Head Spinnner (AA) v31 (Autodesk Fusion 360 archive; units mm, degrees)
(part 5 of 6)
sketch "Female Battery Hole Extrude" plane through (0, 0, 0) normal (0, 0, 1) x axis (-1, 0, 0)
  curve K1 (-12.6524, -62.4018) -> (-7.672, -65.8891)
  line L1 (-22.2167, -8.1598) -> (-12.6524, -62.4018)
  curve K2 (-18.7294, -3.1795) -> (-22.2167, -8.1598)
  line L2 (40.2396, 7.2184) -> (-18.7294, -3.1795)
  curve K3 (45.2199, 3.7311) -> (40.2396, 7.2184)
  line L3 (54.7843, -50.5109) -> (45.2199, 3.7311)
  curve K4 (51.297, -55.4912) -> (54.7843, -50.5109)
  line L4 (-7.672, -65.8891) -> (51.297, -55.4912)
  line L5 (-17.3761, 80.7925) -> (-11.3045, 81.8631)
  line L6 (-17.8953, 83.7374) -> (-17.3761, 80.7925)
  line L7 (-11.8237, 84.808) -> (-17.8953, 83.7374)
  line L8 (-11.3045, 81.8631) -> (-11.8237, 84.808)
  line L9 (85.5727, 3.0826) -> (82.5824, 3.0826)
  line L10 (85.5727, -3.0826) -> (85.5727, 3.0826)
  line L11 (82.5824, -3.0826) -> (85.5727, -3.0826)
  line L12 (82.5824, 3.0826) -> (82.5824, -3.0826)
  line L13 (-19.3992, -80.3308) -> (-25.3341, -78.661)
  line L14 (-20.2091, -83.2093) -> (-19.3992, -80.3308)
  line L15 (-26.144, -81.5395) -> (-20.2091, -83.2093)
  line L16 (-25.3341, -78.661) -> (-26.144, -81.5395)
  line L17 (-55.9395, 9.9372) -> (-55.803, 9.163)
  line L18 (-39.2687, 12.0784) -> (-39.4052, 12.8526)
  line L19 (-32.6329, -25.5549) -> (-32.7694, -24.7807)
  line L20 (-49.3038, -27.6962) -> (-49.1673, -28.4703)
  line L21 (-27.4486, 68.7829) -> (-24.3215, 51.0478)
  curve K5 (-27.4486, 68.7829) -> (-27.4528, 68.8072)
  curve K6 (-27.4528, 68.8072) -> (-25.9276, 70.9853)
  curve K7 (-25.9276, 70.9853) -> (-25.9034, 70.9897)
  line L22 (0.0613, 75.568) -> (-25.9034, 70.9897)
  curve K8 (0.0613, 75.568) -> (0.0856, 75.5721)
  curve K9 (0.0856, 75.5721) -> (2.2637, 74.047)
  curve K10 (2.2637, 74.047) -> (2.2681, 74.0227)
  line L23 (5.3953, 56.2877) -> (2.2681, 74.0227)
  curve K11 (5.3953, 56.2877) -> (5.3994, 56.2634)
  curve K12 (5.3994, 56.2634) -> (3.8743, 54.0853)
  curve K13 (3.8743, 54.0853) -> (3.8501, 54.0809)
  line L24 (-22.1146, 49.5026) -> (3.8501, 54.0809)
  curve K14 (-22.1146, 49.5026) -> (-22.1389, 49.4985)
  curve K15 (-22.1389, 49.4985) -> (-24.317, 51.0236)
  curve K16 (-24.317, 51.0236) -> (-24.3215, 51.0478)
  line L25 (51.5523, -28.2749) -> (50.8842, -28.3927)
  line L26 (60.5772, -26.6836) -> (51.5523, -28.2749)
  line L27 (58.8129, -16.6779) -> (60.5772, -26.6836)
  line L28 (49.12, -18.3871) -> (58.8129, -16.6779)
  line L29 (50.8842, -28.3927) -> (49.12, -18.3871)
  line L30 (8.4191, 15.2675) -> (10.7551, 2.0195)
  line L31 (8.4191, 15.2675) -> (10.7551, 2.0195)
  line L32 (-18.3167, -30.278) -> (-28.0097, -31.9871)
  line L33 (-28.0097, -31.9871) -> (-26.2454, -41.9928)
  line L34 (-26.2454, -41.9928) -> (-17.2205, -40.4014)
  line L35 (-16.5524, -40.2836) -> (-17.2205, -40.4014)
  circle C1 centre (-22.1247, -36.1078) radius 1.5
  circle C2 centre (14.6103, -82.8593) radius 1.804
  circle C3 centre (-49.1147, 68.3144) radius 1.804
  circle C4 centre (22.7878, 80.9928) radius 1.804
  circle C5 centre (-55.6726, -63.0847) radius 1.804
  circle C6 centre (73.8914, -40.2391) radius 1.804
  circle C7 centre (-84.0329, 4.1939) radius 1.804
  circle C8 centre (77.5307, 32.6819) radius 1.804
  circle C9 centre (0, 0) radius 88.9
  arc A1 centre (-44.2862, -7.8089) radius 20.5105 clockwise from (-49.3038, -27.6962) to (-55.803, 9.163)
  arc A2 centre (-47.6724, 11.3949) radius 8.3947 clockwise from (-55.9395, 9.9372) to (-39.4052, 12.8526)
  arc A3 centre (-44.2862, -7.8089) radius 20.5105 clockwise from (-39.2687, 12.0784) to (-32.7694, -24.7807)
  arc A4 centre (-40.9001, -27.0126) radius 8.3947 clockwise from (-32.6329, -25.5549) to (-49.1673, -28.4703)
  circle C10 centre (54.6922, -22.5629) radius 1.5
  point P58 (50.8842, -28.3927)
  point P62 (49.12, -18.3871)
  point P63 (50.0021, -23.3899)
  point P65 (10.7551, 2.0195)
  point P59 (51.5523, -28.2749)
  point P72 (-17.2205, -40.4014)
  point P60 (60.5772, -26.6836)
  point P71 (-26.2454, -41.9928)
  point P61 (58.8129, -16.6779)
  point P69 (-28.0097, -31.9871)
  point P70 (-18.3167, -30.278)
  point P67 (10.7551, 2.0195)
  point P66 (8.4191, 15.2675)
  point P68 (8.4191, 15.2675)
  point P73 (-16.5524, -40.2836)
  point P64 (54.6922, -22.5629)
  coincident L3 P58
  perpendicular L3 L25
  perpendicular L3 L26
  perpendicular L26 L27
  coincident L3 P62
  perpendicular L3 L28
  midpoint L29 P63
  midpoint L3 P63
  midpoint L2 P65
  perpendicular L2 L30
  symmetric P59 L30 P72
  symmetric P60 L30 P71
  symmetric P61 L30 P69
  symmetric P62 L30 P70
  symmetric P65 L30 P67
  symmetric P66 L30 P68
  coincident L1 P73
  perpendicular L1 L35
  dimension "d581" distance L28 P64 = 5.08
  dimension "d582" distance L27 P64 = 5.08
extrude "Extrude44" add sketch "Female Battery Hole Extrude" profile of C1 L1 L3 L25 L26 L27 L28 L29 C10 L32 L33 L34 L35 along normal blind 6.35
chamfer "Chamfer4" distance 1.524
fillet "Fillet8" radius 2.54
chamfer "Chamfer8" distance 1.27
sketch "Battery Hole Shrink" plane through (0, 0, -0.635) normal (0, 0, -1) x axis (1, 0, 0)
  line L1 (21.9717, -8.4882) -> (26.8326, -36.0558)
  curve K1 (21.9445, -7.8065) -> (21.9717, -8.4882)
  curve K2 (21.9445, -7.8065) -> (18.6743, -3.4921)
  line L2 (-40.2947, 6.9057) -> (18.6743, -3.4921)
  curve K3 (-40.2947, 6.9057) -> (-44.8427, 3.9746)
  curve K4 (-45.1031, 3.3367) -> (-44.8427, 3.9746)
  line L3 (-59.0984, -20.9038) -> (-45.1031, 3.3367)
  line L4 (-54.5392, -50.1825) -> (-59.4001, -22.6149)
  curve K5 (-54.512, -50.8642) -> (-54.5392, -50.1825)
  curve K6 (-54.512, -50.8642) -> (-51.2418, -55.1786)
  line L5 (7.7272, -65.5764) -> (-51.2418, -55.1786)
  curve K7 (7.7272, -65.5764) -> (12.2752, -62.6453)
  curve K8 (12.5356, -62.0074) -> (12.2752, -62.6453)
  line L6 (26.5309, -37.7669) -> (12.5356, -62.0074)
  curve K9 (-42.7185, 3.29) -> (-40.6806, 4.717)
  line L7 (18.2884, -5.6809) -> (-40.6806, 4.717)
  curve K10 (18.2884, -5.6809) -> (19.7153, -7.7188)
  line L8 (10.151, -61.9607) -> (19.7153, -7.7188)
  curve K11 (10.151, -61.9607) -> (8.1131, -63.3877)
  line L9 (-50.8559, -52.9898) -> (8.1131, -63.3877)
  curve K12 (-50.8559, -52.9898) -> (-52.2828, -50.9519)
  line L10 (-42.7185, 3.29) -> (-52.2828, -50.9519)
  circle C1 centre (-54.6922, -22.5629) radius 1.5
  circle C2 centre (22.1247, -36.1078) radius 1.5
  arc A1 centre (24.3312, -36.4969) radius 2.54 clockwise from (26.8326, -36.0558) to (26.5309, -37.7669)
  arc A2 centre (-56.8987, -22.1738) radius 2.54 clockwise from (-59.4001, -22.6149) to (-59.0984, -20.9038)
  circle C3 centre (-54.6922, -22.5629) radius 1.45
  circle C4 centre (22.1247, -36.1078) radius 1.45
  concentric C1 C3
  concentric C2 C4
  equal C3 C4
  dimension "d588" diameter C3 = 2.9
extrude "Extrude45" add sketch "Battery Hole Shrink" profile of C1 C2 C3 C4 against normal blind 6.985
remove_instance "RemoveInstance1"
sketch "AAA Battey Holder Wires" plane through (0.021, -0.1193, 0) normal (0.1736, -0.9848, 0) x axis (0.9848, 0.1736, 0)
  line L1 (18.997, 1.27) -> (-40.8817, 1.27)
  line L2 (18.997, 17.78) -> (18.997, 1.27)
  line L3 (-40.8817, 17.78) -> (18.997, 17.78)
  line L4 (-40.8817, 1.27) -> (-40.8817, 17.78)
  line L5 (3.7077, 0.54) -> (3.7077, 7.54)
  line L6 (4.9577, 7.54) -> (4.9577, 0.54)
  line L7 (5.5162, 15.24) -> (14.4062, 15.24)
  line L8 (-12.7111, 15.24) -> (5.5162, 15.24)
  line L9 (4.9577, 7.54) -> (3.7077, 7.54)
  line L10 (4.3327, 16.8158) -> (4.3327, 7.54)
  line L11 (10.6827, 15.24) -> (-2.0173, 15.24)
  line L12 (10.6827, 10.795) -> (10.6827, 15.24)
  line L13 (-2.0173, 10.795) -> (10.6827, 10.795)
  line L14 (-2.0173, 15.24) -> (-2.0173, 10.795)
  point P13 (5.5162, 15.24)
  point P14 (5.5162, 15.24)
  point P11 (3.7077, 7.54)
  point P16 (3.7077, 7.54)
  point P10 (4.9577, 7.54)
  point P17 (4.9577, 7.54)
  point P18 (4.3327, 7.54)
  point P24 (4.3327, 15.24)
  point P22 (10.6827, 10.795)
  point P23 (-2.0173, 10.795)
  point P20 (-2.0173, 15.24)
  coincident P13 P14
  parallel L7 L8
  coincident P11 P16
  coincident P10 P17
  midpoint L9 P18
  perpendicular L8 L10
  horizontal L11
  vertical L12
  horizontal L13
  vertical L14
  midpoint L11 P24
  coincident L8 P24
  coincident L10 P24
  dimension "d591" distance P22 P23 = 12.7
  dimension "d592" distance P20 P23 = 4.445
extrude "Extrude46" cut sketch "AAA Battey Holder Wires" profile of L7 L11 L12 L13 L14 against normal blind 10.16
component_from_bodies "Body->Comp4"
sketch "Motor Switch Fill" plane through (0, 0, 12.7) normal (0, 0, 1) x axis (-1, 0, 0)
  line L1 (-1.252, 71.3831) -> (-23.238, 67.5064)
  line L2 (1.1847, 57.5642) -> (-1.252, 71.3831)
  line L3 (-20.8014, 53.6874) -> (1.1847, 57.5642)
  line L4 (-23.238, 67.5064) -> (-20.8014, 53.6874)
  line L5 (1.085, 73.8986) -> (4.241, 55.9997)
  line L6 (-25.7793, 69.8065) -> (0.3493, 74.4137)
  line L7 (-23.1383, 51.172) -> (-26.2943, 69.0709)
  line L8 (3.7259, 55.2641) -> (-22.4027, 50.6569)
  line L9 (-21.5225, 52.6576) -> (2.2146, 56.8431)
  line L10 (-24.2679, 68.2275) -> (-21.5225, 52.6576)
  line L11 (-0.5308, 72.413) -> (-24.2679, 68.2275)
  line L12 (2.2146, 56.8431) -> (-0.5308, 72.413)
  line L13 (-20.6983, 53.8346) -> (1.0376, 57.6672)
  line L14 (-23.0909, 67.4034) -> (-20.6983, 53.8346)
  line L15 (-1.355, 71.236) -> (-23.0909, 67.4034)
  line L16 (1.0376, 57.6672) -> (-1.355, 71.236)
  line L17 (-1.5314, 72.2366) -> (-1.3071, 70.9646)
  line L18 (1.214, 56.6666) -> (1.0376, 57.6672)
  line L19 (-20.5219, 52.834) -> (-20.6983, 53.8346)
  line L20 (-23.2673, 68.4039) -> (-23.0909, 67.4034)
  closed curve K1 centre (3.6157, 55.8894)
  closed curve K2 centre (0.4596, 73.7883)
  closed curve K3 centre (-25.669, 69.1812)
  closed curve K4 centre (-22.5129, 51.2822)
  point P26 (-1.3071, 70.9646)
  point P27 (-1.5314, 72.2366)
  point P28 (1.214, 56.6666)
  point P29 (-20.5219, 52.834)
  point P30 (-23.2673, 68.4039)
  coincident L16 P26
  coincident L11 P27
  perpendicular L11 L17
  coincident L9 P28
  perpendicular L9 L18
  coincident L9 P29
  perpendicular L9 L19
  coincident L11 P30
  perpendicular L11 L20
  dimension "d595" = -0.889
  dimension "d596" = 0.127 (= "clearance / 2")
extrude "Extrude47" add sketch "Motor Switch Fill" profile of L12 L10 L9 L11 L16 L14 L17 L18 L19 L20 against normal blind 15.24
sketch "Pot Flat Face Cut" plane through (-88.9, 0, 0) normal (1, 0, 0) x axis (0, 1, 0)
  curve K1 (0, 41.9735) -> (0, 34.2265)
  curve K2 (0, 34.2265) -> (0, 41.9735)
  line L1 (0, 41.9735) -> (0, 34.2265)
  circle C1 centre (0, 38.1) radius 5.8102
  point P2 (0, 34.2265)
  point P5 (0, 34.2265)
  point P3 (0, 41.9735)
  point P6 (0, 41.9735)
  point P4 (0, 38.1)
  coincident P2 P5
  coincident P3 P6
  midpoint P4 L1
  dimension "d629" diameter C1 = 11.6205
extrude "Extrude11" cut sketch "Pot Flat Face Cut" profile of K1 K2 C1 along normal blind 0.254
chamfer "Chamfer6" distance 0.254
fillet "Fillet1" radius 0.635
sketch "Motor Controller Housing Material Cut" plane through (-58.7622, 0, 0) normal (1, 0, 0) x axis (0, 1, 0)
  line L1 (-16.2941, 60.325) -> (16.2941, 60.325)
  line L2 (-16.2941, 51.4477) -> (-16.2941, 60.325)
  line L3 (16.2941, 51.4477) -> (-16.2941, 51.4477)
  line L4 (16.2941, 60.325) -> (16.2941, 51.4477)
  line L5 (-1.397, 55.2577) -> (1.397, 55.2577)
  line L6 (-1.397, 60.325) -> (-1.397, 55.2577)
  line L7 (1.397, 60.325) -> (-1.397, 60.325)
  line L8 (1.397, 55.2577) -> (1.397, 60.325)
  line L9 (-7.493, 55.2577) -> (-7.493, 60.325)
  line L10 (-10.287, 55.2577) -> (-7.493, 55.2577)
  line L11 (-10.287, 60.325) -> (-10.287, 55.2577)
  line L12 (10.287, 55.2577) -> (10.287, 60.325)
  line L13 (7.493, 55.2577) -> (10.287, 55.2577)
  line L14 (7.493, 60.325) -> (7.493, 55.2577)
  line L15 (-16.2941, 55.2577) -> (16.2941, 55.2577)
  point P8 (-1.397, 60.325)
  point P10 (0, 60.325)
  point P11 (0, 60.325)
  point P20 (16.2941, 55.2577)
  point P21 (-16.2941, 55.2577)
  point P6 (1.397, 55.2577)
  point P7 (-1.397, 55.2577)
  horizontal L5
  vertical L6
  horizontal L7
  vertical L8
  coincident L1 P8
  midpoint L1 P10
  midpoint L7 P11
  coincident P10 P11
  coincident L4 P20
  coincident L2 P21
  perpendicular L2 L15
  collinear L10 L15
  dimension "d635" distance L3 L5 = 3.81
  dimension "d636" distance P6 P7 = 2.794
  dimension "d639" R-Pattern1-uDistance = 8.89
  dimension "d640" R-Pattern1-vDistance = 0
extrude "Extrude12" cut sketch "Motor Controller Housing Material Cut" profile of L1 L2 L4 L6 L8 L9 L11 L12 L14 L15 against normal blind 24.8666
sketch "Gasket" plane through (0, 0, 60.325) normal (0, 0, -1) x axis (1, 0, 0)
  line L1 (-58.7622, 7.493) -> (-58.7622, 10.287)
  line L2 (-83.6288, 7.493) -> (-58.7622, 7.493)
  line L3 (-83.6288, 1.397) -> (-83.6288, 7.493)
  line L4 (-58.7622, 1.397) -> (-83.6288, 1.397)
  line L5 (-58.7622, -1.397) -> (-58.7622, 1.397)
  line L6 (-83.6288, -1.397) -> (-58.7622, -1.397)
  line L7 (-83.6288, -7.493) -> (-83.6288, -1.397)
  line L8 (-58.7622, -7.493) -> (-83.6288, -7.493)
  line L9 (-58.7622, -10.287) -> (-58.7622, -7.493)
  line L10 (-83.6288, -10.287) -> (-58.7622, -10.287)
  line L11 (-83.6288, -16.2941) -> (-83.6288, -10.287)
  line L12 (-58.7622, -16.2941) -> (-83.6288, -16.2941)
  line L13 (-58.7622, -18.8341) -> (-58.7622, -16.2941)
  line L14 (-83.6305, -18.8341) -> (-58.7622, -18.8341)
  line L15 (-58.7622, 18.8341) -> (-83.6305, 18.8341)
  line L16 (-58.7622, 16.2941) -> (-58.7622, 18.8341)
  line L17 (-83.6288, 16.2941) -> (-58.7622, 16.2941)
  line L18 (-83.6288, 10.287) -> (-83.6288, 16.2941)
  line L19 (-58.7622, 10.287) -> (-83.6288, 10.287)
  line L20 (-41.3411, -8.2894) -> (-49.7744, -11.3589)
  line L21 (2.5431, 50.9906) -> (0.9847, 42.1525)
  line L22 (13.4917, 39.9472) -> (15.0501, 48.7853)
  line L23 (42.8876, -27.6977) -> (36.0128, -21.929)
  line L24 (27.8494, -31.6578) -> (34.7242, -37.4264)
  line L25 (-45.4307, -23.293) -> (-36.9975, -20.2235)
  line L26 (-38.7289, 28.933) -> (-35.5184, 26.2391)
  line L27 (-35.2186, 33.1164) -> (-38.7289, 28.933)
  line L28 (-32.0081, 30.4224) -> (-35.2186, 33.1164)
  line L29 (-35.5184, 26.2391) -> (-32.0081, 30.4224)
  line L30 (-11.0703, -47.0584) -> (-5.6923, -48.0067)
  line L31 (-10.3425, -42.9311) -> (-11.0703, -47.0584)
  line L32 (-4.9645, -43.8794) -> (-10.3425, -42.9311)
  line L33 (-5.6923, -48.0067) -> (-4.9645, -43.8794)
  line L34 (44.4212, 19.0737) -> (40.4829, 17.6403)
  line L35 (46.2889, 13.9421) -> (44.4212, 19.0737)
  line L36 (42.3507, 12.5086) -> (46.2889, 13.9421)
  line L37 (40.4829, 17.6403) -> (42.3507, 12.5086)
  line L38 (-45.554, -23.6081) -> (-37.1151, -20.5366)
  line L39 (27.8529, -31.9922) -> (34.7323, -37.7648)
  line L40 (43.2222, -27.6469) -> (36.3428, -21.8743)
  line L41 (13.7797, 40.1174) -> (15.3391, 48.9614)
  line L42 (2.3318, 51.255) -> (0.7723, 42.411)
  line L43 (-41.6325, -8.1252) -> (-50.0714, -11.1967)
  line L44 (-31.6503, 30.4537) -> (-35.2499, 33.4742)
  line L45 (-35.4871, 25.8812) -> (-31.6503, 30.4537)
  line L46 (-39.0867, 28.9017) -> (-35.4871, 25.8812)
  line L47 (-35.2499, 33.4742) -> (-39.0867, 28.9017)
  line L48 (-4.6702, -43.6733) -> (-10.5486, -42.6368)
  line L49 (-5.4862, -48.301) -> (-4.6702, -43.6733)
  line L50 (-11.3645, -47.2644) -> (-5.4862, -48.301)
  line L51 (-10.5486, -42.6368) -> (-11.3645, -47.2644)
  line L52 (44.573, 19.3993) -> (40.1573, 17.7921)
  line L53 (46.6145, 13.7902) -> (44.573, 19.3993)
  line L54 (42.1989, 12.1831) -> (46.6145, 13.7902)
  line L55 (40.1573, 17.7921) -> (42.1989, 12.1831)
  circle C1 centre (55.6548, -57.4817) radius 1.5875
  circle C2 centre (43.6561, -67.0503) radius 1.5875
  circle C3 centre (-10.2408, -79.3519) radius 1.5875
  circle C4 centre (-25.2029, -75.9369) radius 1.5875
  circle C5 centre (-68.4248, -41.4686) radius 1.5875
  circle C6 centre (-75.0836, -27.6415) radius 1.5875
  circle C7 centre (-75.0836, 27.6415) radius 1.5875
  circle C8 centre (-68.4248, 41.4686) radius 1.5875
  circle C9 centre (-25.2029, 75.9369) radius 1.5875
  circle C10 centre (-10.2408, 79.3519) radius 1.5875
  circle C11 centre (43.6561, 67.0503) radius 1.5875
  circle C12 centre (55.6548, 57.4817) radius 1.5875
  circle C13 centre (79.6412, 7.6735) radius 1.5875
  circle C14 centre (79.6412, -7.6735) radius 1.5875
  circle C15 centre (49.8854, -62.5543) radius 3.6788
  circle C16 centre (-72.0865, 34.715) radius 3.6788
  circle C17 centre (80.01, 0) radius 3.6788
  circle C18 centre (-17.8039, -78.004) radius 3.6788
  circle C19 centre (-17.8039, 78.004) radius 3.6788
  circle C20 centre (49.8854, 62.5543) radius 3.6788
  circle C21 centre (-72.0865, -34.715) radius 3.6788
  arc A1 centre (0, 0) radius 85.725 clockwise from (-83.6305, 18.8341) to (-83.6305, -18.8341)
  arc A2 centre (0, 0) radius 51.054 clockwise from (-45.4307, -23.293) to (-49.7744, -11.3589)
  arc A3 centre (0, 0) radius 42.164 clockwise from (-41.3411, -8.2894) to (0.9847, 42.1525)
  arc A4 centre (0, 0) radius 51.054 clockwise from (2.5431, 50.9906) to (15.0501, 48.7853)
  arc A5 centre (0, 0) radius 42.164 clockwise from (13.4917, 39.9472) to (36.0128, -21.929)
  arc A6 centre (0, 0) radius 51.054 clockwise from (42.8876, -27.6977) to (34.7242, -37.4264)
  arc A7 centre (0, 0) radius 42.164 clockwise from (27.8494, -31.6578) to (-36.9975, -20.2235)
  circle C22 centre (0, 0) radius 42.9895
  circle C23 centre (0, 0) radius 54.229
  arc A8 centre (0, 0) radius 51.308 clockwise from (-45.554, -23.6081) to (-50.0714, -11.1967)
  arc A9 centre (0, 0) radius 42.418 clockwise from (27.8529, -31.9922) to (-37.1151, -20.5366)
  arc A10 centre (0, 0) radius 51.308 clockwise from (43.2222, -27.6469) to (34.7323, -37.7648)
  arc A11 centre (0, 0) radius 42.418 clockwise from (13.7797, 40.1174) to (36.3428, -21.8743)
  arc A12 centre (0, 0) radius 51.308 clockwise from (2.3318, 51.255) to (15.3391, 48.9614)
  arc A13 centre (0, 0) radius 42.418 clockwise from (-41.6325, -8.1252) to (0.7723, 42.411)
  concentric A1 C22
  concentric A1 C23
  dimension "d651" distance A7 C22 = 0.8255
  dimension "d653" distance A6 C23 = 3.175
extrude "Extrude1" new body sketch "Gasket" profile of C22 C23 A8 L40 L38 L39 A10 L41 A12 L42 L43 L44 L47 L45 L46 L48 L49 L50 L51 L52 L54 L53 L55 along normal blind 3.175
sketch "Revolve Limit" plane through (0, 0, 57.15) normal (0, 0, -1) x axis (1, 0, 0)
  line L1 (-45.554, -23.6081) -> (-37.6587, -20.7345)
  line L2 (-42.1761, -8.323) -> (-50.0714, -11.1967)
  line L3 (2.3318, 51.255) -> (0.8728, 42.9806)
  line L4 (13.8801, 40.6871) -> (15.3391, 48.9614)
  line L5 (43.2222, -27.6469) -> (36.7859, -22.2462)
  line L6 (28.296, -32.3641) -> (34.7323, -37.7648)
  line L7 (42.1989, 12.1831) -> (46.6145, 13.7902)
  line L8 (40.1573, 17.7921) -> (42.1989, 12.1831)
  line L9 (44.573, 19.3993) -> (40.1573, 17.7921)
  line L10 (46.6145, 13.7902) -> (44.573, 19.3993)
  line L11 (-39.0867, 28.9017) -> (-35.4871, 25.8812)
  line L12 (-35.2499, 33.4742) -> (-39.0867, 28.9017)
  line L13 (-31.6503, 30.4537) -> (-35.2499, 33.4742)
  line L14 (-35.4871, 25.8812) -> (-31.6503, 30.4537)
  line L15 (-11.3645, -47.2644) -> (-5.4862, -48.301)
  line L16 (-10.5486, -42.6368) -> (-11.3645, -47.2644)
  line L17 (-4.6702, -43.6733) -> (-10.5486, -42.6368)
  line L18 (-5.4862, -48.301) -> (-4.6702, -43.6733)
  arc A1 centre (0, 0) radius 42.9895 clockwise from (28.296, -32.3641) to (-37.6587, -20.7345)
  arc A2 centre (0, 0) radius 51.308 clockwise from (-45.554, -23.6081) to (-50.0714, -11.1967)
  arc A3 centre (0, 0) radius 42.9895 clockwise from (-42.1761, -8.323) to (0.8728, 42.9806)
  arc A4 centre (0, 0) radius 51.308 clockwise from (2.3318, 51.255) to (15.3391, 48.9614)
  arc A5 centre (0, 0) radius 42.9895 clockwise from (13.8801, 40.6871) to (36.7859, -22.2462)
  arc A6 centre (0, 0) radius 51.308 clockwise from (43.2222, -27.6469) to (34.7323, -37.7648)
  circle C1 centre (0, 0) radius 54.229
  circle C2 centre (0, 0) radius 51.7525
  concentric A1 C2
  dimension "d660" distance A2 C2 = 0.4445 (= "clearance * 1.75")
sketch "Gasket Revolve Profile" plane through (0, 0, 0) normal (1, 0, 0) x axis (0, 1, 0)
  line L1 (51.7525, 57.15) -> (-51.7525, 57.15)
  line L2 (54.229, 57.15) -> (-54.229, 57.15)
  line L3 (54.229, 60.325) -> (-54.229, 60.325)
  line L4 (51.7525, 52.07) -> (54.229, 57.15)
  line L5 (51.7525, 57.15) -> (51.7525, 52.07)
  line L6 (51.054, 52.07) -> (-51.054, 52.07)
  line L7 (51.7525, 57.15) -> (54.229, 57.15)
  point P5 (54.229, 57.15)
  point P8 (54.229, 57.15)
  point P3 (51.7525, 57.15)
  point P10 (51.7525, 57.15)
  point P9 (51.7525, 52.07)
  point P13 (51.7525, 57.15)
  coincident P5 P8
  coincident P3 P10
  perpendicular L2 L5
  coincident P9 L6
  coincident P3 P13
revolve "Revolve1" sketch "Gasket Revolve Profile" AlongAngle 360
chamfer "Chamfer1" distance 0.3175
copy_paste "CutPaste2"
copy_paste "CutPaste3"
copy_paste "CutPaste9"
copy_paste "CutPaste4"
copy_paste "CutPaste1"
copy_paste "CutPaste2"
copy_paste "CutPaste1"
sketch "LED Wire Arc Length" plane through (0, 0, 63.5) normal (0, 0, 1) x axis (-1, 0, 0)
  circle C1 centre (-55.6548, -57.4817) radius 1.5875
  circle C2 centre (-43.6561, -67.0503) radius 1.5875
  circle C3 centre (10.2408, -79.3519) radius 1.5875
  circle C4 centre (25.2029, -75.9369) radius 1.5875
  circle C5 centre (68.4248, -41.4686) radius 1.5875
  circle C6 centre (75.0836, -27.6415) radius 1.5875
  circle C7 centre (75.0836, 27.6415) radius 1.5875
  circle C8 centre (68.4248, 41.4686) radius 1.5875
  circle C9 centre (25.2029, 75.9369) radius 1.5875
  circle C10 centre (10.2408, 79.3519) radius 1.5875
  circle C11 centre (-43.6561, 67.0503) radius 1.5875
  circle C12 centre (-55.6548, 57.4817) radius 1.5875
  circle C13 centre (-79.6412, 7.6735) radius 1.5875
  circle C14 centre (-79.6412, -7.6735) radius 1.5875
  circle C15 centre (-49.8854, -62.5543) radius 3.6788
  circle C16 centre (72.0865, 34.715) radius 3.6788
  circle C17 centre (-80.01, 0) radius 3.6788
  circle C18 centre (17.8039, -78.004) radius 3.6788
  circle C19 centre (17.8039, 78.004) radius 3.6788
  circle C20 centre (-49.8854, 62.5543) radius 3.6788
  circle C21 centre (72.0865, -34.715) radius 3.6788
  circle C22 centre (0, 0) radius 42.164
  circle C23 centre (0, 0) radius 85.725
  arc A1 centre (0, 0) radius 80.01 clockwise from (-49.8854, 62.5543) to (17.8039, 78.004)
  point P12 (-43.6561, 67.0503)
  point P21 (-49.8854, 62.5543)
  point P25 (-49.8854, 62.5543)
  point P20 (17.8039, 78.004)
  point P24 (17.8039, 78.004)
  coincident P12 A1
  coincident P21 P25
  coincident P20 P24
sketch "Sketch81" plane through (0, 0, 63.5) normal (0, 0, 1) x axis (1, 0, 0)
  circle C1 centre (0, 0) radius 41.275
  circle C2 centre (0, 0) radius 42.164
  point P1 (0, 0)
  point P2 (0, 0)
  coincident P1 P2
  dimension "d663" distance C1 C2 = 0.889
extrude "Extrude1" new body sketch "Sketch81" profile of C1 along normal blind 1.5113 bodies "Rubber Circle"
sketch "Sketch1" plane through (0, 0, 3.175) normal (0, 0, 1) x axis (-1, 0, 0)
  circle C1 centre (0, 0) radius 41.91
  circle C2 centre (0, 0) radius 41.275
extrude "Extrude2" cut sketch "Sketch1" against normal blind 20.32
joint "Assemble19" alignAngle 0 alignOffsetX 0 alignOffsetY 0 alignOffsetZ 0
offset_faces "OffsetFaces1" distance -0.7937
component_from_bodies "Body->Comp1"
component_from_bodies "Body->Comp2"
joint "Assemble1" alignAngle 0 alignOffsetX 0 alignOffsetY 0 alignOffsetZ 0
sketch "Sketch82" plane through (0, 0, 64.2176) normal (0, 0, 1) x axis (-1, 0, 0)
  circle C1 centre (0, 0) radius 41.275
  circle C2 centre (0, 0) radius 41.4631
  dimension "d677" = 0.1881 (= "clearance / 1.35")
extrude "Extrude16" new body sketch "Sketch82" along normal blind 1.5875 bodies "Rubber to Plat. Fixture"
sketch "Sketch83" plane through (0, 0, 65.8051) normal (0, 0, 1) x axis (-1, 0, 0)
  circle C1 centre (0, 0) radius 41.4631
  circle C2 centre (0, 0) radius 41.91
  circle C3 centre (0, 0) radius 43.4975
  dimension "d680" = 1.5875
extrude "Extrude17" add sketch "Sketch83" against normal blind 3.81
sketch "Sketch85" plane through (0, 0, 61.9951) normal (0, 0, -1) x axis (1, 0, 0)
  circle C1 centre (0, 0) radius 41.4631
  circle C2 centre (0, 0) radius 43.4975
  circle C3 centre (0, 0) radius 41.91
  circle C4 centre (0, 0) radius 42.6085
  dimension "d686" = 0.6985 (= "clearance * 2.75")
extrude "Extrude19" add sketch "Sketch85" profile of C2 C4 along normal blind 5.969
sketch "Sketch86" plane through (0, 0, 64.2176) normal (0, 0, -1) x axis (1, 0, 0)
  circle C1 centre (0, 0) radius 41.4631
  circle C2 centre (0, 0) radius 31.75
  concentric C1 C2
  dimension "d689" diameter C2 = 63.5
extrude "Extrude20" cut sketch "Sketch86" profile of C2 against normal blind 30.48
offset_faces "OffsetFaces1" distance 0.889
chamfer "Chamfer5" distance 0.635
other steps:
base_feature "Base Feature1" bodies "Rubber Lift"
base_feature "Base Feature1" bodies "Rubber Circle"
base_feature "Base Feature1"
base_feature "Base Feature1" bodies "Rubber Lift"
base_feature "Base Feature1"
base_feature "Base Feature1"
base_feature "Base Feature1" bodies "Shell"
base_feature "Base Feature1" bodies "XY Restriction"
chamfer "Chamfer4" distance 0.8255
extrude "Extrude11" cut sketch "Sketch73" profile of L8 L9 L10 L11 L17 L16 L15 L14 L18 L19 L20 L21 L22 L23 L24 L25 L26 L27 L28 L29 L30 L31 L32 L33 along normal blind 15.24
base_feature "Base Feature1" bodies "Shell"
extrude "Extrude2" cut sketch "Holes for Shell Btm" profile of C4 C5 C6 C7 C8 C9 C10 distance 12.7
extrude "Extrude43" cut sketch "Battery Cover Holes" profile of C1 C2 against normal blind 12.7
create_component "CreateComponent1"
create_component "CreateComponent2"
remove_body "RemoveBody1"
create_component "CreateComponent3"
remove_body "RemoveBody2"
joint_origin "JointOrigin5"
joint_origin "JointOrigin3"
create_component "CreateComponent4"
remove_body "RemoveBody1"
create_component "CreateComponent5"
create_component "CreateComponent6"
joint_origin "JointOrigin3"
joint_origin "JointOrigin4"
joint_origin "JointOrigin6"
joint_origin "JointOrigin8"
joint_origin "JointOrigin7"
create_component "CreateComponent7"
create_component "CreateComponent8"
remove_instance "RemoveInstance1"
remove_instance "RemoveInstance2"
remove_instance "RemoveInstance3"
remove_instance "RemoveInstance4"
create_component "CreateComponent9"
remove_instance "RemoveInstance5"
remove_instance "RemoveInstance6"
create_component "CreateComponent1"
remove_body "RemoveBody1"
remove_instance "RemoveInstance7"
remove_instance "RemoveInstance1"
remove_instance "RemoveInstance8"
remove_instance "RemoveInstance9"
remove_instance "RemoveInstance10"
remove_instance "RemoveInstance11"
joint_origin "JointOrigin8"
create_component "CreateComponent1"
remove_body "RemoveBody1"
joint_origin "JointOrigin9"
joint_origin "JointOrigin1"
create_component "CreateComponent2"
remove_body "RemoveBody2"
joint_origin "JointOrigin7"
joint_origin "JointOrigin8"
joint_origin "JointOrigin9"
joint_origin "JointOrigin3"
joint_origin "JointOrigin10"
remove_instance "RemoveInstance12"
joint_origin "JointOrigin4"
create_component "CreateComponent10"
remove_body "RemoveBody3"
create_component "CreateComponent11"
remove_instance "RemoveInstance13"
remove_instance "RemoveInstance14"
remove_instance "RemoveInstance15"
remove_instance "RemoveInstance16"
remove_instance "RemoveInstance17"
remove_instance "RemoveInstance18"
remove_instance "RemoveInstance19"
create_component "CreateComponent1"
remove_instance "RemoveInstance2" sketch "Profile"
remove_instance "RemoveInstance3" sketch "Profile"
remove_instance "RemoveInstance4"
remove_instance "RemoveInstance5"
joint_origin "JointOrigin12"
remove_body "RemoveBody2"
joint_origin "JointOrigin10"
joint_origin "JointOrigin5"
joint_origin "JointOrigin13"
create_component "CreateComponent13"
remove_body "RemoveBody5"
joint_origin "JointOrigin14"
joint_origin "JointOrigin5"
joint_origin "JointOrigin12"
create_component "CreateComponent14"
remove_instance "RemoveInstance21"
remove_instance "RemoveInstance22"
remove_instance "RemoveInstance23"
remove_instance "RemoveInstance24"
create_component "CreateComponent15"
remove_instance "RemoveInstance25"
remove_instance "RemoveInstance26"
remove_instance "RemoveInstance1"
joint_origin "JointOrigin4"
joint_origin "JointOrigin6"
create_component "CreateComponent1"
remove_body "RemoveBody1"
create_component "CreateComponent2"
remove_body "RemoveBody2"
joint_origin "JointOrigin1"
joint_origin "JointOrigin1"
named bodies: "Shell", "Rubber Lift", "Bottom", "XY Restriction", "Rubber Circle", "Rubber to Plat. Fixture"

design "9V Battery & T Connector"
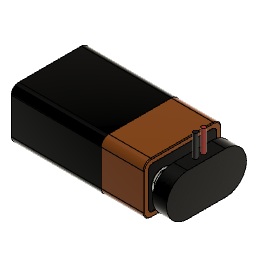
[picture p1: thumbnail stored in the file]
base_feature "Base Feature1"
base_feature "Base Feature1"
base_feature "Base Feature1" bodies "Clip", "Negative", "Positive"
joint "Assemble1" alignAngle 180 alignOffsetX 0 alignOffsetY 0 alignOffsetZ 0.381
move "Move1"
move "Move2"
remove_body "RemoveBody1"
remove_body "RemoveBody2"
sketch "Sketch1" plane through (2.5021, 1.948, 15.621) normal (0, 0, 1) x axis (-1, 0, 0)
  line L1 (-25.3765, -86.0759) -> (-38.0765, -86.0759)
  line L2 (-25.3765, -81.3769) -> (-25.3765, -86.0759)
  line L3 (-38.0765, -81.3769) -> (-25.3765, -81.3769)
  line L4 (-38.0765, -86.0759) -> (-38.0765, -81.3769)
  line L5 (-31.7265, -86.0759) -> (-31.7265, -81.3769)
  line L6 (-25.3765, -83.7264) -> (-31.7265, -83.7264)
  circle C1 centre (-30.3295, -83.7264) radius 0.6922
  circle C2 centre (-33.1235, -83.7264) radius 0.6922
  point P6 (-31.7265, -81.3769)
  point P7 (-31.7265, -86.0759)
  point P8 (-31.7265, -83.7264)
  point P9 (-25.3765, -83.7264)
  point P10 (-30.3295, -83.7264)
  midpoint L3 P6
  midpoint L1 P7
  midpoint L5 P8
  midpoint L2 P9
  coincident L6 P10
  symmetric L5 C1 C2
  dimension "d25" diameter C1 = 1.3843
  dimension "d26" distance L5 P10 = 1.397
extrude "Extrude1" new body sketch "Sketch1" profile of C1 C2 along normal blind 7.62 bodies "Negative", "Positive"
position "Position2"
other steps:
create_component "CreateComponent1"
create_component "CreateComponent1"
create_component "CreateComponent2"
joint_origin "JointOrigin1"
joint_origin "JointOrigin1"
named bodies: "Clip", "Negative", "Positive"

design "DC 6V 5RPM 2-Wire Motor"
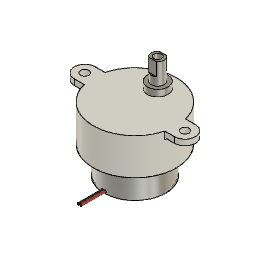
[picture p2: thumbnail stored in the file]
parameter "wireLength" = 9.525
sketch "Motor Profile" plane through (0, 0, 0) normal (0, 0, 1) x axis (1, 0, 0)
  circle C1 centre (0, 0) radius 12.0332
  point P1 (0, 0)
  point P2 (0, 0)
  coincident P1 P2
  dimension "d6" diameter C1 = 24.0665
extrude "Extrude1" new body sketch "Motor Profile" along normal blind 10.4267
sketch "Gear Box Profile" plane through (0, 0, 10.4267) normal (0, 0, 1) x axis (-1, 0, 0)
  circle C1 centre (0, 0) radius 12.0332
  circle C2 centre (0, 0) radius 16.1925
  point P1 (0, 0)
  point P3 (0, 0)
  coincident P1 P3
  dimension "d3" diameter C2 = 32.385
extrude "Extrude2" new body sketch "Gear Box Profile" along normal blind 14.3764
sketch "Mounting Holes" plane through (0, 0, 24.8031) normal (0, 0, 1) x axis (-1, 0, 0)
  line L1 (19.5, 4.0767) -> (-19.5, 4.0767)
  line L2 (19.5, -4.0767) -> (19.5, 4.0767)
  line L3 (-19.5, -4.0767) -> (19.5, -4.0767)
  line L4 (-19.5, 4.0767) -> (-19.5, -4.0767)
  line L5 (19.5, -4.0767) -> (-19.5, 4.0767)
  line L6 (-19.5, -4.0767) -> (19.5, 4.0767)
  line L7 (-17.875, 0) -> (17.875, 0)
  line L8 (17.875, 0) -> (19.5, 0)
  line L9 (-17.875, 0) -> (-19.5, 0)
  circle C1 centre (0, 0) radius 16.1925
  arc A1 centre (-19.5, 0) radius 4.0767 clockwise from (-19.5, -4.0767) to (-19.5, 4.0767)
  arc A2 centre (19.5, 0) radius 4.0767 clockwise from (19.5, 4.0767) to (19.5, -4.0767)
  circle C2 centre (19.5, 0) radius 1.625
  circle C3 centre (-19.5, 0) radius 1.625
  point P7 (0, 0)
  point P1 (0, 0)
  point P12 (17.875, 0)
  point P13 (-17.875, 0)
  point P10 (19.5, 0)
  point P14 (19.5, 0)
  point P8 (-19.5, 0)
  point P15 (-19.5, 0)
  point P4 (19.5, 4.0767)
  point P5 (19.5, -4.0767)
  point P9 (19.5, 0)
  point P11 (-19.5, 0)
  horizontal L1
  perpendicular L1 L2
  parallel L1 L3
  parallel L2 L4
  coincident L5 P7
  coincident L6 P7
  coincident P1 P7
  tangent L3 A1
  tangent L3 A2
  concentric A2 C2
  concentric A1 C3
  equal C2 C3
  coincident C2 P12
  coincident C3 P13
  horizontal L7
  coincident P10 P14
  coincident P8 P15
  horizontal L9
  dimension "d7" distance P4 P5 = 8.1534
  dimension "d9" diameter C2 = 3.25
  dimension "d41" distance P9 P11 = 39
extrude "Extrude3" add sketch "Mounting Holes" profile of C1 L1 L3 A1 A2 C2 C3 against normal blind 2.2479
sketch "Shaft" plane through (0, 0, 24.8031) normal (0, 0, 1) x axis (-1, 0, 0)
  line L1 (-19.5, 4.0767) -> (-15.6709, 4.0767)
  line L2 (-15.6709, -4.0767) -> (-19.5, -4.0767)
  line L3 (19.5, -4.0767) -> (15.6709, -4.0767)
  line L4 (15.6709, 4.0767) -> (19.5, 4.0767)
  line L5 (0, -16.1925) -> (0, 0)
  circle C1 centre (-19.5, 0) radius 1.625
  circle C2 centre (19.5, 0) radius 1.625
  arc A1 centre (0, 0) radius 16.1925 clockwise from (-15.6709, 4.0767) to (15.6709, 4.0767)
  arc A2 centre (-19.5, 0) radius 4.0767 clockwise from (-19.5, -4.0767) to (-19.5, 4.0767)
  arc A3 centre (0, 0) radius 16.1925 clockwise from (15.6709, -4.0767) to (-15.6709, -4.0767)
  arc A4 centre (19.5, 0) radius 4.0767 clockwise from (19.5, 4.0767) to (19.5, -4.0767)
  circle C3 centre (0, -8.89) radius 4.0005
  point P1 (0, 0)
  point P13 (0, 0)
  point P14 (0, -16.1925)
  point P15 (0, -8.89)
  point P6 (0, 0)
  coincident P1 P13
  midpoint A3 P14
  coincident L5 P15
  dimension "d12" diameter C3 = 8.001
  dimension "d13" distance P6 P15 = 8.89
extrude "Extrude4" new body sketch "Shaft" profile of C3 along normal blind 2.54
sketch "Shaft (1)" plane through (0, 0, 27.3431) normal (0, 0, 1) x axis (-1, 0, 0)
  circle C1 centre (0, -8.89) radius 4.0005
  circle C2 centre (0, -8.89) radius 2.4956
  concentric C1 C2
  dimension "d16" diameter C2 = 4.9911
extrude "Extrude5" add sketch "Shaft (1)" profile of C2 along normal blind 3.175
sketch "Shaft (2)" plane through (0, 0, 30.5181) normal (0, 0, 1) x axis (-1, 0, 0)
  line L1 (-1.4922, -6.8898) -> (1.4922, -6.8898)
  line L2 (-1.4922, -10.8902) -> (1.4922, -10.8902)
  line L3 (0, -6.8898) -> (0, -10.8903)
  circle C1 centre (0, -8.89) radius 2.4956
  point P3 (1.4922, -6.8898)
  point P4 (-1.4922, -6.8898)
  point P5 (1.4922, -10.8902)
  point P6 (-1.4922, -10.8902)
  point P7 (0, -10.8903)
  point P8 (0, -6.8898)
  coincident C1 P3
  coincident C1 P4
  horizontal L1
  coincident C1 P5
  coincident C1 P6
  parallel L1 L2
  midpoint L2 P7
  midpoint L1 P8
  equal L1 L2
  dimension "d19" distance P7 P8 = 4.0005
extrude "Extrude6" add sketch "Shaft (2)" profile of C1 L1 L2 along normal blind 5.1308
chamfer "Chamfer1" distance 0.762
sketch "Sketch7" plane through (0, 0, 0) normal (0, 0, -1) x axis (1, 0, 0)
  circle C1 centre (0, 0) radius 12.0332
  circle C2 centre (0, 0) radius 3.175
  point P1 (0, 0)
  point P3 (0, 0)
  coincident P1 P3
  dimension "d23" diameter C2 = 6.35
extrude "Extrude7" add sketch "Sketch7" profile of C2 along normal blind 1.0922
fillet "Fillet1" radius 0.508
sketch "Sketch8" plane through (0, 0, 0) normal (0, 0, -1) x axis (1, 0, 0)
  circle C1 centre (0, 0) radius 3.175
  circle C2 centre (0, 0) radius 12.0332
  circle C3 centre (0, 0) radius 11.7157
  dimension "d28" = -0.3175
extrude "Extrude8" cut sketch "Sketch8" profile of C1 C3 against normal blind 0.635 (magnitude of "( -0.05 / 2 ) * 1 in")
work_plane "WorkPlane1" RotateAngle 0
sketch "Wires" plane through (0, -12.0332, 0) normal (0, -1, 0) x axis (-1, 0, 0)
  line L1 (0, 8.001) -> (0, 0)
  circle C1 centre (0.508, -0.889) radius 0.4255
  circle C2 centre (-0.508, -0.889) radius 0.4255
  point P1 (0, 0)
  point P2 (0, 0)
  point P4 (0.508, -0.889)
  coincident P1 P2
  vertical L1
  symmetric L1 C1 C2
  dimension "d32" distance L1 P4 = 0.508
  dimension "d33" diameter C1 = 0.8509
  dimension "d34" distance P1 P4 = 0.889
extrude "Extrude9" add sketch "Wires" profile of C1 C2 distance 9.525 (= "wireLength")
fillet "Fillet2" radius 0.1905
sketch "Sketch10" plane through (0, 0, 35.6489) normal (0, 0, 1) x axis (-1, 0, 0)
  line L1 (-1.4922, -6.8898) -> (1.4922, -6.8898)
  line L2 (1.4922, -10.8902) -> (-1.4922, -10.8902)
  arc A1 centre (0, -8.89) radius 2.4956 clockwise from (-1.4922, -10.8902) to (-1.4922, -6.8898)
  arc A2 centre (0, -8.89) radius 2.4956 clockwise from (1.4922, -6.8898) to (1.4922, -10.8902)
  circle C1 centre (0, -8.89) radius 1.5
  concentric A1 C1
  dimension "d42" diameter C1 = 3
extrude "Extrude10" cut sketch "Sketch10" profile of C1 against normal blind 31.75
chamfer "Chamfer2" distance 0.0254

design "Plastic Latching Push Button"
sketch "Sketch1" plane through (0, 0, 0) normal (0, 0, 1) x axis (1, 0, 0)
  circle C1 centre (0, 0) radius 6.096
  point P1 (0, 0)
  point P2 (0, 0)
  coincident P1 P2
  dimension "d1" diameter C1 = 12.192
extrude "Extrude1" new body sketch "Sketch1" along normal blind 17.8562
sketch "Sketch6" plane through (0, 0, 0) normal (0, 0, -1) x axis (1, 0, 0)
  circle C1 centre (0, 0) radius 6.096
  circle C2 centre (0, 0) radius 5.588
  point P1 (0, 0)
  point P3 (0, 0)
  coincident P1 P3
  dimension "d25" diameter C2 = 11.176
extrude "Extrude6" cut sketch "Sketch6" against normal blind 7.874
sketch "Sketch2" plane through (0, 0, 17.8562) normal (0, 0, 1) x axis (-1, 0, 0)
  circle C1 centre (0, 0) radius 6.096
  circle C2 centre (0, 0) radius 7.1374
  point P2 (0, 0)
  point P4 (0, 0)
  coincident P2 P4
  dimension "d4" diameter C2 = 14.2748
extrude "Extrude2" add sketch "Sketch2" + "Sketch6" profile of S1:C1 S1:C2 blind 2.3495
sketch "Sketch3" plane through (0, 0, 20.2057) normal (0, 0, 1) x axis (-1, 0, 0)
  circle C1 centre (0, 0) radius 7.1374
  circle C2 centre (0, 0) radius 4.5021
  concentric C1 C2
  dimension "d7" diameter C2 = 9.0043
extrude "Extrude3" add sketch "Sketch3" + "Sketch6" profile of S1:C2 blind 3.8735
chamfer "Chamfer1" sketch "Sketch6" distance 1.524
fillet "Fillet1" radius 0.254
sketch "Sketch4" plane through (0, 0, 0) normal (0, 0, -1) x axis (1, 0, 0)
  line L1 (0, -6.096) -> (0, 0)
  line L2 (6.096, 0) -> (0, 0)
  line L3 (4.826, -0.9969) -> (4.2418, -0.997)
  line L4 (4.826, 0.997) -> (4.826, -0.9969)
  line L5 (4.2418, 0.9969) -> (4.826, 0.997)
  line L6 (4.2418, -0.997) -> (4.2418, 0.9969)
  line L7 (4.826, 0.997) -> (4.2418, -0.997)
  line L8 (4.2418, 0.9969) -> (4.826, -0.9969)
  line L9 (-4.826, -0.9969) -> (-4.2418, -0.997)
  line L10 (-4.826, 0.997) -> (-4.826, -0.9969)
  line L11 (-4.2418, 0.9969) -> (-4.826, 0.997)
  line L12 (-4.2418, -0.997) -> (-4.2418, 0.9969)
  circle C1 centre (0, 0) radius 5.588
  point P9 (4.5339, 0)
  point P5 (4.2418, -0.997)
  point P10 (-4.2418, -0.997)
  point P6 (4.826, -0.9969)
  point P11 (-4.826, -0.9969)
  point P7 (4.826, 0.997)
  point P12 (-4.826, 0.997)
  point P8 (4.2418, 0.9969)
  point P13 (-4.2418, 0.9969)
  point P4 (6.096, 0)
  vertical L1
  perpendicular L1 L2
  horizontal L3
  perpendicular L3 L4
  parallel L3 L5
  parallel L4 L6
  coincident L7 P9
  coincident L8 P9
  coincident L2 P9
  symmetric L1 P5 P10
  symmetric L1 P6 P11
  symmetric L1 P7 P12
  symmetric L1 P8 P13
  dimension "d13" distance P5 P8 = 1.9939
  dimension "d14" distance P5 P6 = 0.5842
  dimension "d15" distance P4 L4 = 1.27
extrude "Extrude4" new body sketch "Sketch4" profile of L3 L4 L5 L6 L9 L10 L11 L12 along normal blind 5.461
sketch "Sketch5" plane through (4.826, 0, 0) normal (1, 0, 0) x axis (0, 1, 0)
  line L1 (-0.997, -5.461) -> (-0.997, 0)
  line L2 (0.9969, -5.461) -> (-0.997, -5.461)
  line L3 (0.9969, 0) -> (0.9969, -5.461)
  line L4 (-0.3175, -4.191) -> (0.3175, -4.191)
  line L5 (-0.3175, -2.921) -> (-0.3175, -4.191)
  line L6 (0.3175, -2.921) -> (-0.3175, -2.921)
  line L7 (0.3175, -4.191) -> (0.3175, -2.921)
  line L8 (-0.3175, -2.921) -> (0.3175, -4.191)
  line L9 (0.3175, -2.921) -> (-0.3175, -4.191)
  line L10 (0, -5.461) -> (0, 0)
  line L11 (-0.997, 0) -> (0.9969, 0)
  point P10 (0, -3.556)
  point P1 (0, 0)
  point P11 (0, 0)
  point P12 (0, -5.461)
  point P6 (0.3175, -4.191)
  point P7 (-0.3175, -4.191)
  point P9 (0.3175, -2.921)
  horizontal L4
  perpendicular L4 L5
  parallel L4 L6
  parallel L5 L7
  coincident L8 P10
  coincident L9 P10
  coincident P1 P11
  midpoint L2 P12
  coincident P10 L10
  dimension "d18" distance P6 P7 = 0.635
  dimension "d19" distance P6 P9 = 1.27
  dimension "d20" distance L2 L4 = 1.27
extrude "Extrude5" cut sketch "Sketch5" + "Sketch6" profile of S1:L4 S1:L5 S1:L6 S1:L7 blind -19.05
fillet "Fillet2" radius 0.254

design "3 State Switch"
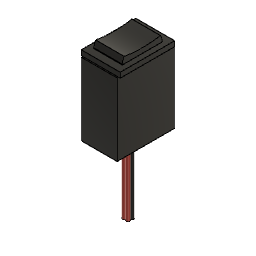
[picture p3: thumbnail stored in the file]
sketch "Sketch1" plane through (0, 0, 0) normal (0, 0, 1) x axis (1, 0, 0)
  line L1 (-7.512, -10.522) -> (7.5121, -10.5219)
  line L2 (-7.512, 10.522) -> (-7.512, -10.522)
  line L3 (7.5121, 10.522) -> (-7.512, 10.522)
  line L4 (7.5121, -10.5219) -> (7.5121, 10.522)
  line L5 (-7.512, 10.522) -> (7.5121, -10.5219)
  line L6 (7.5121, 10.522) -> (-7.512, -10.522)
  line L7 (-5.4927, -7.6936) -> (5.4927, -7.6936)
  line L8 (-5.4927, 7.6936) -> (-5.4927, -7.6936)
  line L9 (5.4927, 7.6936) -> (-5.4927, 7.6936)
  line L10 (5.4927, -7.6936) -> (5.4927, 7.6936)
  line L11 (-5.4927, 7.6936) -> (5.4927, -7.6936)
  line L12 (5.4927, 7.6936) -> (-5.4927, -7.6936)
  point P6 (0, 0)
  point P1 (0, 0)
  point P11 (0, 0)
  point P7 (5.4927, -7.6936)
  point P2 (7.5121, -10.5219)
  point P3 (-7.512, -10.522)
  point P5 (7.5121, 10.522)
  point P8 (-5.4927, -7.6936)
  horizontal L1
  perpendicular L1 L2
  parallel L1 L3
  parallel L2 L4
  coincident L5 P6
  coincident L6 P6
  coincident P1 P6
  horizontal L7
  perpendicular L7 L8
  parallel L7 L9
  parallel L8 L10
  coincident L11 P11
  coincident L12 P11
  coincident L5 P7
  coincident P6 P11
  dimension "d1" distance P2 P3 = 15.0241
  dimension "d2" distance P2 P5 = 21.0439
  dimension "d3" distance P7 P8 = 10.9855
extrude "Extrude1" new body sketch "Sketch1" profile of L1 L2 L3 L4 L7 L8 L9 L10 against normal blind 1.9812
extrude "Extrude2" new body sketch "Sketch1" profile of L7 L8 L9 L10 along normal blind 2.54
sketch "Sketch2" plane through (0, 0, -1.9812) normal (0, 0, -1) x axis (1, 0, 0)
  line L1 (7.5121, -10.522) -> (-7.512, -10.522)
  line L2 (7.5121, 10.5219) -> (7.5121, -10.522)
  line L3 (-7.512, 10.522) -> (7.5121, 10.5219)
  line L4 (-7.512, -10.522) -> (-7.512, 10.522)
  line L5 (6.8453, 11.0236) -> (-6.8453, 11.0236)
  line L6 (6.8453, -11.0236) -> (6.8453, 11.0236)
  line L7 (-6.8453, -11.0236) -> (6.8453, -11.0236)
  line L8 (-6.8453, 11.0236) -> (-6.8453, -11.0236)
  line L9 (6.8453, -11.0236) -> (-6.8453, 11.0236)
  line L10 (-6.8453, -11.0236) -> (6.8453, 11.0236)
  point P10 (0, 0)
  point P1 (0, 0)
  point P8 (6.8453, -11.0236)
  point P9 (-6.8453, -11.0236)
  point P6 (-6.8453, 11.0236)
  horizontal L5
  perpendicular L5 L6
  parallel L5 L7
  parallel L6 L8
  coincident L9 P10
  coincident L10 P10
  coincident P1 P10
  dimension "d8" distance P8 P9 = 13.6906
  dimension "d9" distance P6 P9 = 22.0472
extrude "Extrude3" add sketch "Sketch2" profile of L1 L3 L5 L6 L7 L8 along normal blind 27.94
sketch "Sketch3" plane through (-5.4927, 0, 0) normal (-1, 0, 0) x axis (0, -1, 0)
  line L1 (7.6936, 0) -> (-7.6936, 0)
  line L2 (7.6936, 2.54) -> (7.6936, 0)
  line L3 (-7.6936, 2.54) -> (7.6936, 2.54)
  line L4 (-7.6936, 0) -> (-7.6936, 2.54)
  line L5 (6.985, 2.54) -> (-6.985, 2.54)
  line L6 (0, 0) -> (0, 2.54)
  arc A1 centre (0, 39.9942) radius 38.1 clockwise from (6.985, 2.54) to (-6.985, 2.54)
  arc A2 centre (-3.2504, 0.1294) radius 4.445 clockwise from (-7.6936, 0) to (-6.985, 2.54)
  arc A3 centre (3.2504, 0.1294) radius 4.445 clockwise from (6.985, 2.54) to (7.6936, 0)
  point P8 (6.985, 2.54)
  point P6 (-6.985, 2.54)
  point P9 (0, 2.54)
  point P1 (0, 0)
  point P10 (0, 0)
  point P2 (-7.6936, 0)
  point P11 (-7.6936, 0)
  point P14 (6.985, 2.54)
  point P15 (7.6936, 0)
  coincident L3 P8
  coincident L3 P6
  coincident L3 P8
  midpoint L5 P9
  coincident P1 P10
  vertical L6
  coincident P2 P11
  symmetric P6 L6 P14
  symmetric L6 P11 P15
  symmetric L6 A2 A3
  dimension "d12" distance P6 P8 = 13.97
  dimension "d13" radius A1 = 38.1
  dimension "d14" radius A2 = 4.445
extrude "Extrude4" cut sketch "Sketch3" profile of L2 L3 L4 A1 A2 A3 against normal blind 22.86
sketch "Sketch4" plane through (0, 0, -29.9212) normal (0, 0, -1) x axis (1, 0, 0)
  line L1 (6.8453, -11.0236) -> (-6.8453, -11.0236)
  line L2 (6.8453, 11.0236) -> (6.8453, -11.0236)
  line L3 (-6.8453, 11.0236) -> (6.8453, 11.0236)
  line L4 (-6.8453, -11.0236) -> (-6.8453, 11.0236)
  line L5 (0.7061, 0.7061) -> (-0.7061, 0.7061)
  line L6 (0.7061, -0.7061) -> (0.7061, 0.7061)
  line L7 (-0.7061, -0.7061) -> (0.7061, -0.7061)
  line L8 (-0.7061, 0.7061) -> (-0.7061, -0.7061)
  line L9 (0.7061, -0.7061) -> (-0.7061, 0.7061)
  line L10 (-0.7061, -0.7061) -> (0.7061, 0.7061)
  circle C1 centre (-0.7061, 0.7061) radius 0.7061
  circle C2 centre (-0.7061, -0.7061) radius 0.7061
  circle C3 centre (0.7061, -0.7061) radius 0.7061
  circle C4 centre (0.7061, 0.7061) radius 0.7061
  point P10 (0, 0)
  point P1 (0, 0)
  point P6 (-0.7061, 0.7061)
  point P11 (-0.7061, 0.7061)
  point P9 (-0.7061, -0.7061)
  point P12 (-0.7061, -0.7061)
  point P8 (0.7061, -0.7061)
  point P13 (0.7061, -0.7061)
  point P7 (0.7061, 0.7061)
  point P14 (0.7061, 0.7061)
  horizontal L5
  perpendicular L5 L6
  parallel L5 L7
  parallel L6 L8
  coincident L9 P10
  coincident L10 P10
  coincident P1 P10
  equal L5 L8
  coincident P6 P11
  coincident P9 P12
  coincident P8 P13
  coincident P7 P14
  equal C1 C4
  equal C1 C2
  equal C2 C3
  tangent C3 C4
extrude "Extrude5" new body sketch "Sketch4" profile of C1 C2 C3 C4 along normal blind 27.94

design "LED + Cap"
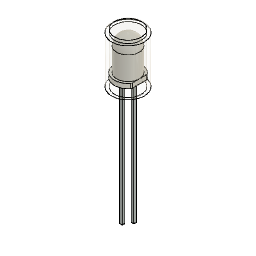
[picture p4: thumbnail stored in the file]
base_feature "Base Feature"
sketch "Sketch1" plane through (0, 0, 0) normal (0, 0, 1) x axis (1, 0, 0)
  circle C1 centre (0, 0) radius 3.5941
  point P1 (0, 0)
  point P2 (0, 0)
  coincident P1 P2
  dimension "d1_2" diameter C1 = 7.1882
extrude "Extrude1" new body sketch "Sketch1" along normal blind 10.9474 named "d2_2"
shell "Shell1" innerThickness 0.635 named "d4_2"
fillet "Fillet1" radius 0.635 named "d6_1"
joint "Assemble2" alignAngle 0 alignOffsetX 0 alignOffsetY 0 alignOffsetZ 2.5019
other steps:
create_component "CreateComponent1"
create_component "CreateComponent2"
create_component "CreateComponent3"
create_component "CreateComponent4"
create_component "CreateComponent5"
create_component "CreateComponent1"
create_component "CreateComponent2"
joint_origin "JointOrigin2"
joint_origin "JointOrigin2"

design "6V AA Battery Holder"
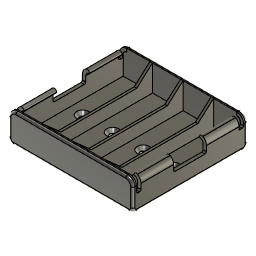
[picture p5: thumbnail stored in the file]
sketch "XY Profile" plane through (0, 0, 0) normal (0, 0, 1) x axis (1, 0, 0)
  line L1 (-31, 28.6) -> (31, 28.6)
  line L2 (-31, -28.6) -> (-31, 28.6)
  line L3 (31, -28.6) -> (-31, -28.6)
  line L4 (31, 28.6) -> (31, -28.6)
  line L5 (-31, -28.6) -> (31, 28.6)
  line L6 (31, -28.6) -> (-31, 28.6)
  point P6 (0, 0)
  point P1 (0, 0)
  point P4 (-31, -28.6)
  point P5 (31, -28.6)
  point P3 (-31, 28.6)
  horizontal L1
  perpendicular L1 L2
  parallel L1 L3
  parallel L2 L4
  coincident L5 P6
  coincident L6 P6
  coincident P1 P6
  dimension "d1" distance P4 P5 = 62 (= "Linear Dimension-2")
  dimension "d2" distance P3 P4 = 57.2 (= "Linear Dimension-3")
extrude "Extrude1" new body sketch "XY Profile" profile of L1 L2 L3 L4 no distance stored
fillet "Fillet1" ChordLen 5
shell "Shell1" innerThickness 1.7
sketch "Seperator" plane through (0, 0, 0) normal (1, 0, 0) x axis (0, 1, 0)
  line L1 (-28.6, 11.1645) -> (-28.6, 14.7)
  line L2 (28.6, 14.7) -> (28.6, 11.1645)
  line L3 (-26.8, 14.7) -> (-28.6, 14.7)
  line L4 (-26.8, 7.8) -> (-26.8, 14.7)
  line L5 (-24.5, 7.8) -> (-26.8, 7.8)
  line L6 (-24.5, 14.7) -> (-24.5, 7.8)
  line L7 (-8.2, 14.7) -> (-24.5, 14.7)
  line L8 (-8.2, 7.8) -> (-8.2, 14.7)
  line L9 (8.2, 7.8) -> (-8.2, 7.8)
  line L10 (8.2, 14.7) -> (8.2, 7.8)
  line L11 (24.5, 14.7) -> (8.2, 14.7)
  line L12 (24.5, 9.7206) -> (24.5, 14.7)
  line L13 (26.8, 9.7206) -> (24.5, 9.7206)
  line L14 (26.8, 14.7) -> (26.8, 9.7206)
  line L15 (28.6, 14.7) -> (26.8, 14.7)
  line L16 (26.9, 14.7) -> (28.6, 14.7)
  line L17 (-28.6, 14.7) -> (-26.9, 14.7)
  line L18 (28.6, 0) -> (-28.6, 0)
  line L19 (24.5, 14.7) -> (26.8, 14.7)
  line L20 (8.2, 14.7) -> (-8.2, 14.7)
  line L21 (-24.5, 14.7) -> (-26.8, 14.7)
  point P2 (-28.6, 14.7)
  point P6 (-28.6, 14.7)
  point P5 (28.6, 14.7)
  point P19 (28.6, 14.7)
  point P18 (26.8, 14.7)
  point P7 (-26.8, 14.7)
  point P12 (-8.2, 7.8)
  point P13 (8.2, 7.8)
  point P1 (0, 0)
  point P16 (24.5, 9.7206)
  point P17 (26.8, 9.7206)
  coincident P2 P6
  perpendicular L1 L3
  perpendicular L3 L4
  perpendicular L4 L5
  perpendicular L5 L6
  perpendicular L6 L7
  perpendicular L7 L8
  perpendicular L8 L9
  perpendicular L7 L10
  perpendicular L8 L11
  perpendicular L11 L12
  perpendicular L12 L13
  perpendicular L13 L14
  coincident P5 P19
  perpendicular L14 L15
  equal L7 L11
  equal L5 L13
  collinear L11 L15
  collinear L3 L7
  equal L6 L8
  dimension "d8" distance P18 P19 = 1.8
  dimension "d9" distance P6 P7 = 1.8 (= "d8")
  dimension "d10" distance P12 P13 = 16.4
  dimension "d11" distance P1 L9 = 7.8
  dimension "d12" distance P16 P17 = 2.3
extrude "Extrude2" cut sketch "Seperator" profile of L4 L5 L6 L8 L9 L10 L12 L13 L14 L19 L20 L21 distance 43
fillet "Fillet2" ChordLen 1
